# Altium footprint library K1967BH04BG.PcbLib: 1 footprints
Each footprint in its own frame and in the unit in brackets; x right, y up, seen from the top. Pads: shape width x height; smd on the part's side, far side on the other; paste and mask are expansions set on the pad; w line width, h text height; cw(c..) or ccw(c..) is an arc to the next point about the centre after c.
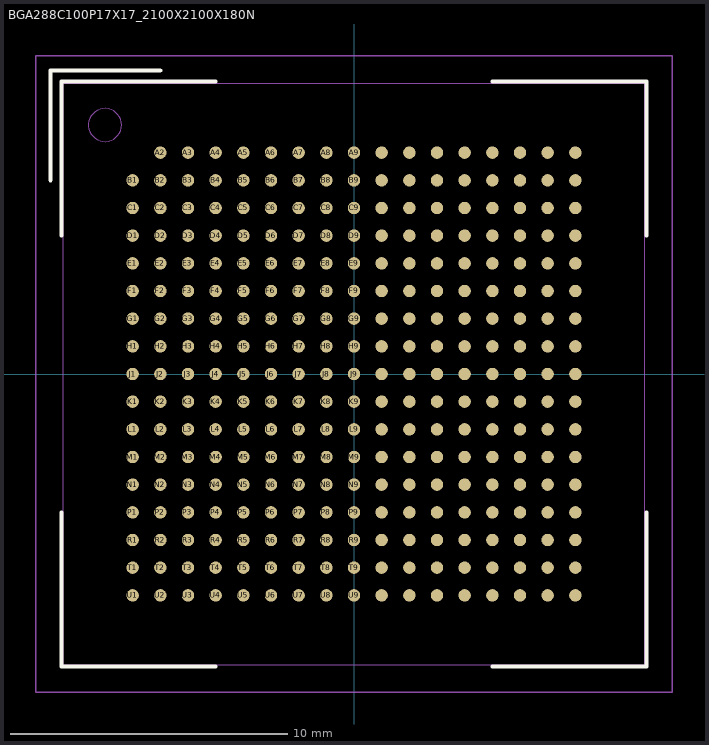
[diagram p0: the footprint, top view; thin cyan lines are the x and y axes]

## BGA288C100P17X17_2100X2100X180N [mm] "288-BGA, 1.00 mm pitch, 21.00 X 21.00 X 1.80 mm body, ball 0.6 mm"
height 1.8
pads (288):
  round 0.45 smd mask+0.05: A2(-7,8) A3(-6,8) A4(-5,8) A5(-4,8) A6(-3,8) A7(-2,8) A8(-1,8) A9(0,8) A10(1,8) A11(2,8) A12(3,8) A13(4,8) A14(5,8) A15(6,8) A16(7,8) A17(8,8) B1(-8,7) B2(-7,7) B3(-6,7) B4(-5,7) B5(-4,7) B6(-3,7) B7(-2,7) B8(-1,7) B9(0,7) B10(1,7) B11(2,7) B12(3,7) B13(4,7) B14(5,7) B15(6,7) B16(7,7) B17(8,7) C1(-8,6) C2(-7,6) C3(-6,6) C4(-5,6) C5(-4,6) C6(-3,6) C7(-2,6) C8(-1,6) C9(0,6) C10(1,6) C11(2,6) C12(3,6) C13(4,6) C14(5,6) C15(6,6) C16(7,6) C17(8,6) D1(-8,5) D2(-7,5) D3(-6,5) D4(-5,5) D5(-4,5) D6(-3,5) D7(-2,5) D8(-1,5) D9(0,5) D10(1,5) D11(2,5) D12(3,5) D13(4,5) D14(5,5) D15(6,5) D16(7,5) D17(8,5) E1(-8,4) E2(-7,4) E3(-6,4) E4(-5,4) E5(-4,4) E6(-3,4) E7(-2,4) E8(-1,4) E9(0,4) E10(1,4) E11(2,4) E12(3,4) E13(4,4) E14(5,4) E15(6,4) E16(7,4) E17(8,4) F1(-8,3) F2(-7,3) F3(-6,3) F4(-5,3) F5(-4,3) F6(-3,3) F7(-2,3) F8(-1,3) F9(0,3) F10(1,3) F11(2,3) F12(3,3) F13(4,3) F14(5,3) F15(6,3) F16(7,3) F17(8,3) G1(-8,2) G2(-7,2) G3(-6,2) G4(-5,2) G5(-4,2) G6(-3,2) G7(-2,2) G8(-1,2) G9(0,2) G10(1,2) G11(2,2) G12(3,2) G13(4,2) G14(5,2) G15(6,2) G16(7,2) G17(8,2) H1(-8,1) H2(-7,1) H3(-6,1) H4(-5,1) H5(-4,1) H6(-3,1) H7(-2,1) H8(-1,1) H9(0,1) H10(1,1) H11(2,1) H12(3,1) H13(4,1) H14(5,1) H15(6,1) H16(7,1) H17(8,1) J1(-8,0) J2(-7,0) J3(-6,0) J4(-5,0) J5(-4,0) J6(-3,0) J7(-2,0) J8(-1,0) J9(0,0) J10(1,0) J11(2,0) J12(3,0) J13(4,0) J14(5,0) J15(6,0) J16(7,0) J17(8,0) K1(-8,-1) K2(-7,-1) K3(-6,-1) K4(-5,-1) K5(-4,-1) K6(-3,-1) K7(-2,-1) K8(-1,-1) K9(0,-1) K10(1,-1) K11(2,-1) K12(3,-1) K13(4,-1) K14(5,-1) K15(6,-1) K16(7,-1) K17(8,-1) L1(-8,-2) L2(-7,-2) L3(-6,-2) L4(-5,-2) L5(-4,-2) L6(-3,-2) L7(-2,-2) L8(-1,-2) L9(0,-2) L10(1,-2) L11(2,-2) L12(3,-2) L13(4,-2) L14(5,-2) L15(6,-2) L16(7,-2) L17(8,-2) M1(-8,-3) M2(-7,-3) M3(-6,-3) M4(-5,-3) M5(-4,-3) M6(-3,-3) M7(-2,-3) M8(-1,-3) M9(0,-3) M10(1,-3) M11(2,-3) M12(3,-3) M13(4,-3) M14(5,-3) M15(6,-3) M16(7,-3) M17(8,-3) N1(-8,-4) N2(-7,-4) N3(-6,-4) N4(-5,-4) N5(-4,-4) N6(-3,-4) N7(-2,-4) N8(-1,-4) N9(0,-4) N10(1,-4) N11(2,-4) N12(3,-4) N13(4,-4) N14(5,-4) N15(6,-4) N16(7,-4) N17(8,-4) P1(-8,-5) P2(-7,-5) P3(-6,-5) P4(-5,-5) P5(-4,-5) P6(-3,-5) P7(-2,-5) P8(-1,-5) P9(0,-5) P10(1,-5) P11(2,-5) P12(3,-5) P13(4,-5) P14(5,-5) P15(6,-5) P16(7,-5) P17(8,-5) R1(-8,-6) R2(-7,-6) R3(-6,-6) R4(-5,-6) R5(-4,-6) R6(-3,-6) R7(-2,-6) R8(-1,-6) R9(0,-6) R10(1,-6) R11(2,-6) R12(3,-6) R13(4,-6) R14(5,-6) R15(6,-6) R16(7,-6) R17(8,-6) T1(-8,-7) T2(-7,-7) T3(-6,-7) T4(-5,-7) T5(-4,-7) T6(-3,-7) T7(-2,-7) T8(-1,-7) T9(0,-7) T10(1,-7) T11(2,-7) T12(3,-7) T13(4,-7) T14(5,-7) T15(6,-7) T16(7,-7) T17(8,-7) U1(-8,-8) U2(-7,-8) U3(-6,-8) U4(-5,-8) U5(-4,-8) U6(-3,-8) U7(-2,-8) U8(-1,-8) U9(0,-8) U10(1,-8) U11(2,-8) U12(3,-8) U13(4,-8) U14(5,-8) U15(6,-8) U16(7,-8) U17(8,-8)
Top Overlay:
  lines w0.15: -10.975,7 -10.975,10.975 -7,10.975 ; -10.575,-5 -10.575,-10.575 -5,-10.575 ; -10.575,5 -10.575,10.575 -5,10.575 ; 5,-10.575 10.575,-10.575 10.575,-5 ; 5,10.575 10.575,10.575 10.575,5
Top Assembly:
  circle w0: c-9,9 r0.6
  lines w0: -10.5,-10.5 -10.5,10.5 10.5,10.5 10.5,-10.5 -10.5,-10.5
  text ".Designator" at -2.621,-0.355 h1.52
Top Courtyard:
  lines w0.05: -11.5,-11.5 -11.5,11.5 11.5,11.5 11.5,-11.5 -11.5,-11.5
3D body "BGA288C100P17X17_2100X2100X180.STEP": height 1.8, standoff 0, extent -10.5,-10.5 10.5,10.5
